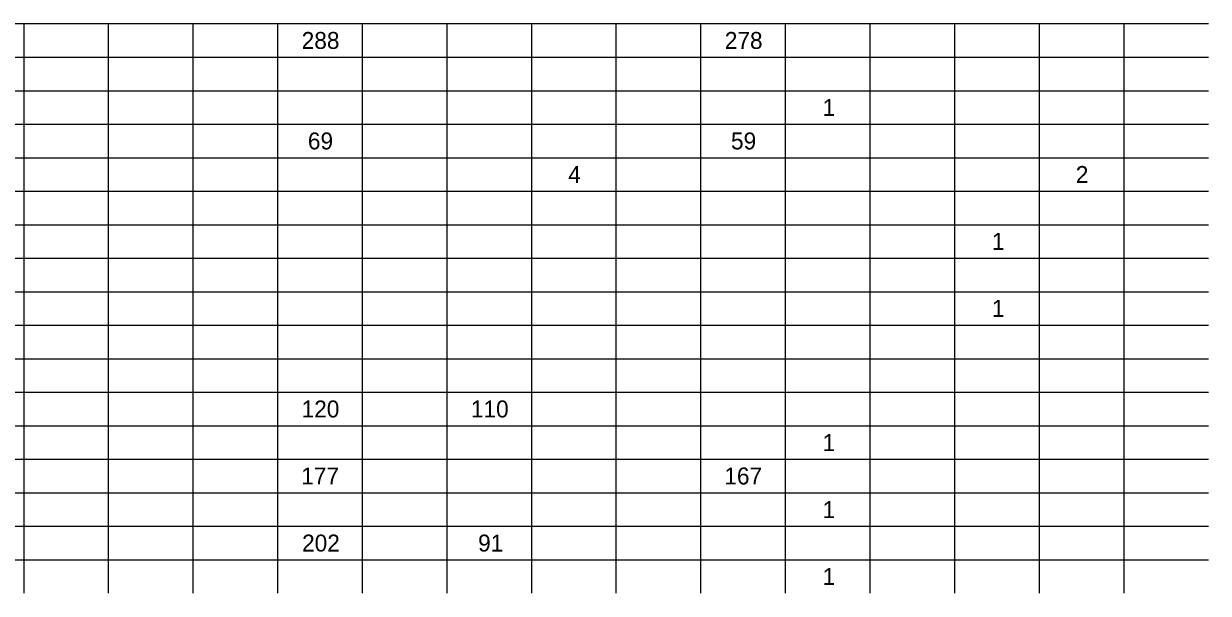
# Model space of a CAD drawing. Extents: x 0 to 34, y 0 to 22.
# Drawn here: x 16.82 to 26.95, y 5.46 to 10.33 of the extents above; entities that cross this region are included whole.
import ezdxf

# ---------------------------------------------------------------- set-up
doc = ezdxf.new("R2010")
doc.units = 0
doc.layers.add('Default', color=7, linetype='Continuous')

msp = doc.modelspace()

# ---------------------------------------------------------------- linework, layer by layer
at = {"layer": 'Default'}
for p, q in [((15.374, 10.331), (16.822, 10.331)), ((16.822, 10.331), (23.336, 10.331)), ((16.822, 10.331), (16.822, 10.044)), ((17.546, 10.331), (17.546, 10.044)), ((18.27, 10.331), (18.27, 10.044)), ((18.993, 10.331), (18.993, 10.044)), ((19.717, 10.331), (19.717, 10.044)), ((20.441, 10.331), (20.441, 10.044)), ((21.165, 10.331), (21.165, 10.044)), ((21.888, 10.331), (21.888, 10.044)), ((22.612, 10.331), (22.612, 10.044)), ((23.336, 10.331), (24.06, 10.331)), ((23.336, 10.331), (23.336, 10.044)), ((24.06, 10.331), (26.231, 10.331)), ((24.06, 10.331), (24.06, 10.044)), ((24.783, 10.331), (24.783, 10.044)), ((25.507, 10.331), (25.507, 10.044)), ((26.231, 10.331), (26.955, 10.331)), ((26.231, 10.331), (26.231, 10.044)), ((15.374, 10.044), (16.822, 10.044)), ((16.822, 10.044), (23.336, 10.044)), ((16.822, 10.044), (16.822, 9.758)), ((17.546, 10.044), (17.546, 9.758)), ((18.27, 10.044), (18.27, 9.758)), ((18.993, 10.044), (18.993, 9.758)), ((19.717, 10.044), (19.717, 9.758)), ((20.441, 10.044), (20.441, 9.758)), ((21.165, 10.044), (21.165, 9.758)), ((21.888, 10.044), (21.888, 9.758)), ((22.612, 10.044), (22.612, 9.758)), ((23.336, 10.044), (24.06, 10.044)), ((23.336, 10.044), (23.336, 9.758)), ((24.06, 10.044), (26.231, 10.044)), ((24.06, 10.044), (24.06, 9.758)), ((24.783, 10.044), (24.783, 9.758)), ((25.507, 10.044), (25.507, 9.758)), ((26.231, 10.044), (26.955, 10.044)), ((26.231, 10.044), (26.231, 9.758)), ((15.374, 9.758), (16.822, 9.758)), ((16.822, 9.758), (23.336, 9.758)), ((16.822, 9.758), (16.822, 9.471)), ((17.546, 9.758), (17.546, 9.471)), ((18.27, 9.758), (18.27, 9.471)), ((18.993, 9.758), (18.993, 9.471)), ((19.717, 9.758), (19.717, 9.471)), ((20.441, 9.758), (20.441, 9.471)), ((21.165, 9.758), (21.165, 9.471)), ((21.888, 9.758), (21.888, 9.471)), ((22.612, 9.758), (22.612, 9.471)), ((23.336, 9.758), (24.06, 9.758)), ((23.336, 9.758), (23.336, 9.471)), ((24.06, 9.758), (26.231, 9.758)), ((24.06, 9.758), (24.06, 9.471)), ((24.783, 9.758), (24.783, 9.471)), ((25.507, 9.758), (25.507, 9.471)), ((26.231, 9.758), (26.955, 9.758)), ((26.231, 9.758), (26.231, 9.471)), ((15.374, 9.471), (16.822, 9.471)), ((16.822, 9.471), (23.336, 9.471)), ((16.822, 9.471), (16.822, 9.185)), ((17.546, 9.471), (17.546, 9.185)), ((18.27, 9.471), (18.27, 9.185)), ((18.993, 9.471), (18.993, 9.185)), ((19.717, 9.471), (19.717, 9.185)), ((20.441, 9.471), (20.441, 9.185)), ((21.165, 9.471), (21.165, 9.185)), ((21.888, 9.471), (21.888, 9.185)), ((22.612, 9.471), (22.612, 9.185)), ((23.336, 9.471), (24.06, 9.471)), ((23.336, 9.471), (23.336, 9.185)), ((24.06, 9.471), (26.231, 9.471)), ((24.06, 9.471), (24.06, 9.185)), ((24.783, 9.471), (24.783, 9.185)), ((25.507, 9.471), (25.507, 9.185)), ((26.231, 9.471), (26.955, 9.471)), ((26.231, 9.471), (26.231, 9.185)), ((15.374, 9.185), (16.822, 9.185)), ((16.822, 9.185), (23.336, 9.185)), ((16.822, 9.185), (16.822, 8.899)), ((17.546, 9.185), (17.546, 8.899)), ((18.27, 9.185), (18.27, 8.899)), ((18.993, 9.185), (18.993, 8.899)), ((19.717, 9.185), (19.717, 8.899)), ((20.441, 9.185), (20.441, 8.899)), ((21.165, 9.185), (21.165, 8.899)), ((21.888, 9.185), (21.888, 8.899)), ((22.612, 9.185), (22.612, 8.899)), ((23.336, 9.185), (24.06, 9.185)), ((23.336, 9.185), (23.336, 8.899)), ((24.06, 9.185), (26.231, 9.185)), ((24.06, 9.185), (24.06, 8.899)), ((24.783, 9.185), (24.783, 8.899)), ((25.507, 9.185), (25.507, 8.899)), ((26.231, 9.185), (26.955, 9.185)), ((26.231, 9.185), (26.231, 8.899)), ((15.374, 8.899), (16.822, 8.899)), ((16.822, 8.899), (23.336, 8.899)), ((16.822, 8.899), (16.822, 8.612)), ((17.546, 8.899), (17.546, 8.612)), ((18.27, 8.899), (18.27, 8.612)), ((18.993, 8.899), (18.993, 8.612)), ((19.717, 8.899), (19.717, 8.612)), ((20.441, 8.899), (20.441, 8.612)), ((21.165, 8.899), (21.165, 8.612)), ((21.888, 8.899), (21.888, 8.612)), ((22.612, 8.899), (22.612, 8.612)), ((23.336, 8.899), (24.06, 8.899)), ((23.336, 8.899), (23.336, 8.612)), ((24.06, 8.899), (26.231, 8.899)), ((24.06, 8.899), (24.06, 8.612)), ((24.783, 8.899), (24.783, 8.612)), ((25.507, 8.899), (25.507, 8.612)), ((26.231, 8.899), (26.955, 8.899)), ((26.231, 8.899), (26.231, 8.612)), ((15.374, 8.612), (16.822, 8.612)), ((16.822, 8.612), (23.336, 8.612)), ((16.822, 8.612), (16.822, 8.326)), ((17.546, 8.612), (17.546, 8.326)), ((18.27, 8.612), (18.27, 8.326)), ((18.993, 8.612), (18.993, 8.326)), ((19.717, 8.612), (19.717, 8.326)), ((20.441, 8.612), (20.441, 8.326)), ((21.165, 8.612), (21.165, 8.326)), ((21.888, 8.612), (21.888, 8.326)), ((22.612, 8.612), (22.612, 8.326)), ((23.336, 8.612), (24.06, 8.612)), ((23.336, 8.612), (23.336, 8.326)), ((24.06, 8.612), (26.231, 8.612)), ((24.06, 8.612), (24.06, 8.326)), ((24.783, 8.612), (24.783, 8.326)), ((25.507, 8.612), (25.507, 8.326)), ((26.231, 8.612), (26.955, 8.612)), ((26.231, 8.612), (26.231, 8.326)), ((15.374, 8.326), (16.822, 8.326)), ((16.822, 8.326), (23.336, 8.326)), ((16.822, 8.326), (16.822, 8.039)), ((17.546, 8.326), (17.546, 8.039)), ((18.27, 8.326), (18.27, 8.039)), ((18.993, 8.326), (18.993, 8.039)), ((19.717, 8.326), (19.717, 8.039)), ((20.441, 8.326), (20.441, 8.039)), ((21.165, 8.326), (21.165, 8.039)), ((21.888, 8.326), (21.888, 8.039)), ((22.612, 8.326), (22.612, 8.039)), ((23.336, 8.326), (24.06, 8.326)), ((23.336, 8.326), (23.336, 8.039)), ((24.06, 8.326), (26.231, 8.326)), ((24.06, 8.326), (24.06, 8.039)), ((24.783, 8.326), (24.783, 8.039)), ((25.507, 8.326), (25.507, 8.039)), ((26.231, 8.326), (26.955, 8.326)), ((26.231, 8.326), (26.231, 8.039)), ((15.374, 8.039), (16.822, 8.039)), ((16.822, 8.039), (23.336, 8.039)), ((16.822, 8.039), (16.822, 7.753)), ((17.546, 8.039), (17.546, 7.753)), ((18.27, 8.039), (18.27, 7.753)), ((18.993, 8.039), (18.993, 7.753)), ((19.717, 8.039), (19.717, 7.753)), ((20.441, 8.039), (20.441, 7.753)), ((21.165, 8.039), (21.165, 7.753)), ((21.888, 8.039), (21.888, 7.753)), ((22.612, 8.039), (22.612, 7.753)), ((23.336, 8.039), (24.06, 8.039)), ((23.336, 8.039), (23.336, 7.753)), ((24.06, 8.039), (26.231, 8.039)), ((24.06, 8.039), (24.06, 7.753)), ((24.783, 8.039), (24.783, 7.753)), ((25.507, 8.039), (25.507, 7.753)), ((26.231, 8.039), (26.955, 8.039)), ((26.231, 8.039), (26.231, 7.753)), ((15.374, 7.753), (16.822, 7.753)), ((16.822, 7.753), (23.336, 7.753)), ((16.822, 7.753), (16.822, 7.467)), ((17.546, 7.753), (17.546, 7.467)), ((18.27, 7.753), (18.27, 7.467)), ((18.993, 7.753), (18.993, 7.467)), ((19.717, 7.753), (19.717, 7.467)), ((20.441, 7.753), (20.441, 7.467)), ((21.165, 7.753), (21.165, 7.467)), ((21.888, 7.753), (21.888, 7.467)), ((22.612, 7.753), (22.612, 7.467)), ((23.336, 7.753), (24.06, 7.753)), ((23.336, 7.753), (23.336, 7.467)), ((24.06, 7.753), (26.231, 7.753)), ((24.06, 7.753), (24.06, 7.467)), ((24.783, 7.753), (24.783, 7.467)), ((25.507, 7.753), (25.507, 7.467)), ((26.231, 7.753), (26.955, 7.753)), ((26.231, 7.753), (26.231, 7.467)), ((15.374, 7.467), (16.822, 7.467)), ((16.822, 7.467), (23.336, 7.467)), ((16.822, 7.467), (16.822, 7.18)), ((17.546, 7.467), (17.546, 7.18)), ((18.27, 7.467), (18.27, 7.18)), ((18.993, 7.467), (18.993, 7.18)), ((19.717, 7.467), (19.717, 7.18)), ((20.441, 7.467), (20.441, 7.18)), ((21.165, 7.467), (21.165, 7.18)), ((21.888, 7.467), (21.888, 7.18)), ((22.612, 7.467), (22.612, 7.18)), ((23.336, 7.467), (24.06, 7.467)), ((23.336, 7.467), (23.336, 7.18)), ((24.06, 7.467), (26.231, 7.467)), ((24.06, 7.467), (24.06, 7.18)), ((24.783, 7.467), (24.783, 7.18)), ((25.507, 7.467), (25.507, 7.18)), ((26.231, 7.467), (26.955, 7.467)), ((26.231, 7.467), (26.231, 7.18)), ((15.374, 7.18), (16.822, 7.18)), ((16.822, 7.18), (23.336, 7.18)), ((16.822, 7.18), (16.822, 6.894)), ((17.546, 7.18), (17.546, 6.894)), ((18.27, 7.18), (18.27, 6.894)), ((18.993, 7.18), (18.993, 6.894)), ((19.717, 7.18), (19.717, 6.894)), ((20.441, 7.18), (20.441, 6.894)), ((21.165, 7.18), (21.165, 6.894)), ((21.888, 7.18), (21.888, 6.894)), ((22.612, 7.18), (22.612, 6.894)), ((23.336, 7.18), (24.06, 7.18)), ((23.336, 7.18), (23.336, 6.894)), ((24.06, 7.18), (26.231, 7.18)), ((24.06, 7.18), (24.06, 6.894)), ((24.783, 7.18), (24.783, 6.894)), ((25.507, 7.18), (25.507, 6.894)), ((26.231, 7.18), (26.955, 7.18)), ((26.231, 7.18), (26.231, 6.894)), ((15.374, 6.894), (16.822, 6.894)), ((16.822, 6.894), (23.336, 6.894)), ((16.822, 6.894), (16.822, 6.607)), ((17.546, 6.894), (17.546, 6.607)), ((18.27, 6.894), (18.27, 6.607)), ((18.993, 6.894), (18.993, 6.607)), ((19.717, 6.894), (19.717, 6.607)), ((20.441, 6.894), (20.441, 6.607)), ((21.165, 6.894), (21.165, 6.607)), ((21.888, 6.894), (21.888, 6.607)), ((22.612, 6.894), (22.612, 6.607)), ((23.336, 6.894), (24.06, 6.894)), ((23.336, 6.894), (23.336, 6.607)), ((24.06, 6.894), (26.231, 6.894)), ((24.06, 6.894), (24.06, 6.607)), ((24.783, 6.894), (24.783, 6.607)), ((25.507, 6.894), (25.507, 6.607)), ((26.231, 6.894), (26.955, 6.894)), ((26.231, 6.894), (26.231, 6.607)), ((15.374, 6.607), (16.822, 6.607)), ((16.822, 6.607), (23.336, 6.607)), ((16.822, 6.607), (16.822, 6.321)), ((17.546, 6.607), (17.546, 6.321)), ((18.27, 6.607), (18.27, 6.321)), ((18.993, 6.607), (18.993, 6.321)), ((19.717, 6.607), (19.717, 6.321)), ((20.441, 6.607), (20.441, 6.321)), ((21.165, 6.607), (21.165, 6.321)), ((21.888, 6.607), (21.888, 6.321)), ((22.612, 6.607), (22.612, 6.321)), ((23.336, 6.607), (24.06, 6.607)), ((23.336, 6.607), (23.336, 6.321)), ((24.06, 6.607), (26.231, 6.607)), ((24.06, 6.607), (24.06, 6.321)), ((24.783, 6.607), (24.783, 6.321)), ((25.507, 6.607), (25.507, 6.321)), ((26.231, 6.607), (26.955, 6.607)), ((26.231, 6.607), (26.231, 6.321)), ((15.374, 6.321), (16.822, 6.321)), ((16.822, 6.321), (23.336, 6.321)), ((16.822, 6.321), (16.822, 6.035)), ((17.546, 6.321), (17.546, 6.035)), ((18.27, 6.321), (18.27, 6.035)), ((18.993, 6.321), (18.993, 6.035)), ((19.717, 6.321), (19.717, 6.035)), ((20.441, 6.321), (20.441, 6.035)), ((21.165, 6.321), (21.165, 6.035)), ((21.888, 6.321), (21.888, 6.035)), ((22.612, 6.321), (22.612, 6.035)), ((23.336, 6.321), (24.06, 6.321)), ((23.336, 6.321), (23.336, 6.035)), ((24.06, 6.321), (26.231, 6.321)), ((24.06, 6.321), (24.06, 6.035)), ((24.783, 6.321), (24.783, 6.035)), ((25.507, 6.321), (25.507, 6.035)), ((26.231, 6.321), (26.955, 6.321)), ((26.231, 6.321), (26.231, 6.035)), ((15.374, 6.035), (16.822, 6.035)), ((16.822, 6.035), (23.336, 6.035)), ((16.822, 6.035), (16.822, 5.748)), ((17.546, 6.035), (17.546, 5.748)), ((18.27, 6.035), (18.27, 5.748)), ((18.993, 6.035), (18.993, 5.748)), ((19.717, 6.035), (19.717, 5.748)), ((20.441, 6.035), (20.441, 5.748)), ((21.165, 6.035), (21.165, 5.748)), ((21.888, 6.035), (21.888, 5.748)), ((22.612, 6.035), (22.612, 5.748)), ((23.336, 6.035), (24.06, 6.035)), ((23.336, 6.035), (23.336, 5.748)), ((24.06, 6.035), (26.231, 6.035)), ((24.06, 6.035), (24.06, 5.748)), ((24.783, 6.035), (24.783, 5.748)), ((25.507, 6.035), (25.507, 5.748)), ((26.231, 6.035), (26.955, 6.035)), ((26.231, 6.035), (26.231, 5.748)), ((15.374, 5.748), (16.822, 5.748)), ((16.822, 5.748), (23.336, 5.748)), ((16.822, 5.748), (16.822, 5.462)), ((17.546, 5.748), (17.546, 5.462)), ((18.27, 5.748), (18.27, 5.462)), ((18.993, 5.748), (18.993, 5.462)), ((19.717, 5.748), (19.717, 5.462)), ((20.441, 5.748), (20.441, 5.462)), ((21.165, 5.748), (21.165, 5.462)), ((21.888, 5.748), (21.888, 5.462)), ((22.612, 5.748), (22.612, 5.462)), ((23.336, 5.748), (24.06, 5.748)), ((23.336, 5.748), (23.336, 5.462)), ((24.06, 5.748), (26.231, 5.748)), ((24.06, 5.748), (24.06, 5.462)), ((24.783, 5.748), (24.783, 5.462)), ((25.507, 5.748), (25.507, 5.462)), ((26.231, 5.748), (26.955, 5.748)), ((26.231, 5.748), (26.231, 5.462))]:
    msp.add_line(p, q, dxfattribs=at)

# ---------------------------------------------------------------- texts
for s, height, p in [('288', 0.1449, (19.2, 10.115)), ('278', 0.1449, (22.819, 10.115)), ('1', 0.145, (23.656, 9.542)), ('69', 0.1449, (19.253, 9.256)), ('59', 0.1449, (22.872, 9.256)), ('4', 0.145, (21.479, 8.969)), ('2', 0.145, (25.821, 8.969)), ('1', 0.145, (25.103, 8.397)), ('1', 0.145, (25.103, 7.824)), ('120', 0.1449, (19.199, 6.965)), ('110', 0.1449, (20.647, 6.965)), ('1', 0.145, (23.656, 6.678)), ('177', 0.1449, (19.196, 6.392)), ('167', 0.1449, (22.815, 6.392)), ('1', 0.145, (23.656, 6.105)), ('202', 0.1449, (19.203, 5.819)), ('91', 0.1449, (20.709, 5.819)), ('1', 0.145, (23.656, 5.533))]:
    msp.add_text(s, height=height, dxfattribs=at).set_placement(p)

doc.saveas('drawing.dxf')
